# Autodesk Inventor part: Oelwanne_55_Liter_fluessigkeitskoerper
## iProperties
Created: 2005-05
Part Number: Oelwanne_55_Liter_fluessigkeitskoerper
Document SubType Name: Modeling
Designer: Mario Wipf
Manufacturer: Standard
Standards Organization: Custom
Material: dichte_null
Author: Mario Wipf
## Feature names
1. Extrusion1
